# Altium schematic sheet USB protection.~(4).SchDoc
size A3; SheetNumber: 3; SheetTotal: 4
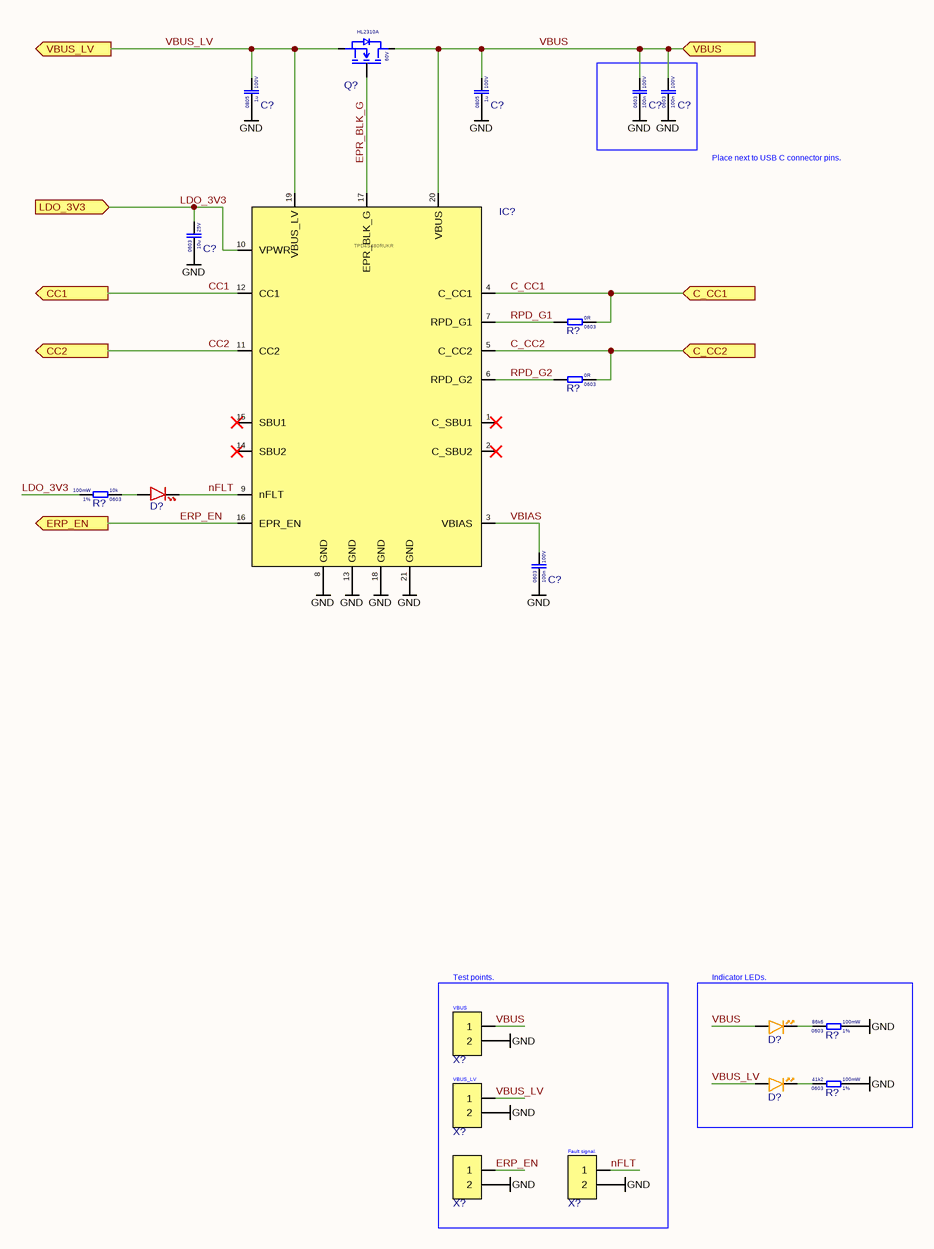
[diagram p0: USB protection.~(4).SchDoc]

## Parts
(Parts that share a designator on the sheet are numbered #1, #2 ... from top to bottom, then left to right.)
C?#1  Voltage Rating: 100V  Case Code (Imperial): 0805  Capacitance: 1u  [Cap_0805]  (hidden comment: CC0805KKX7R0BB105)
C?#2  Voltage Rating: 100V  Case Code (Imperial): 0805  Capacitance: 1u  [Cap_0805]  (hidden comment: CC0805KKX7R0BB105)
C?#3  Voltage Rating: 100V  Case Code (Imperial): 0603  Capacitance: 100n  [CAP 0603]  (hidden comment: CC0603KRX7R0BB104)
C?#4  Voltage Rating: 100V  Case Code (Imperial): 0603  Capacitance: 100n  [CAP 0603]  (hidden comment: CC0603KRX7R0BB104)
C?#5  Voltage Rating: 25V  Case Code (Imperial): 0603  Capacitance: 10u  [CAP 0603]  (hidden comment: CL10A106MA8NRNC)
C?#6  Voltage Rating: 100V  Case Code (Imperial): 0603  Capacitance: 100n  [CAP 0603]  (hidden comment: CC0603KRX7R0BB104)
D?#1  XL-1608SURC-06  [DIODE_0603_RED]  (value not drawn)
D?#2  XL-1608UOC-06  [DIODE_0603_ORANGE]  (value not drawn)
D?#3  XL-1608UOC-06  [DIODE_0603_ORANGE]  (value not drawn)
IC?  TPD4S480RUKR  [WQFN (20)]
Q?  Voltage: 60V  [SOT-23 GSD]  (hidden comment: HL2310A)
R?#1  Resistance: 0R  Case Code (Imperial): 0603  [RES_0603]  (hidden comment: 0603WAF0000T5E)
R?#2  Resistance: 0R  Case Code (Imperial): 0603  [RES_0603]  (hidden comment: 0603WAF0000T5E)
R?#3  Resistance Tolerance: 1%  Resistance: 10k  Power Rating: 100mW  Case Code (Imperial): 0603  [RES_0603]  (hidden comment: 0603WAF1002T5E)
R?#4  Resistance Tolerance: 1%  Resistance: 86k6  Power Rating: 100mW  Case Code (Imperial): 0603  [RES_0603]  (hidden comment: 0603WAF8662T5E)
R?#5  Resistance Tolerance: 1%  Resistance: 41k2  Power Rating: 100mW  Case Code (Imperial): 0603  [RES_0603]  (hidden comment: 0603WAF4122T5E)
X?#1  ZX-PZ1.27-1-2PZZ  [Pin header 1x2 1.27mmP THT Vertical]  (value not drawn)
X?#2  ZX-PZ1.27-1-2PZZ  [Pin header 1x2 1.27mmP THT Vertical]  (value not drawn)
X?#3  ZX-PZ1.27-1-2PZZ  [Pin header 1x2 1.27mmP THT Vertical]  (value not drawn)
X?#4  ZX-PZ1.27-1-2PZZ  [Pin header 1x2 1.27mmP THT Vertical]  (value not drawn)

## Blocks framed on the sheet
Test points.: X?#1-X?#4
Indicator LEDs.: D?#2 D?#3 R?#4 R?#5

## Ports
C_CC1 (in, see CHARGER[7B]), C_CC2 (in, see CHARGER[7B]), CC1 (out, see CHARGER[6B]), CC2 (out, see CHARGER[6B]), ERP_EN (out, see CHARGER[6B]), LDO_3V3 (in, see CHARGER[6C]), VBUS (in, see CHARGER[7B]), VBUS_LV (out, see CHARGER[6B])

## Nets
GND: C?#1.1 C?#2.1 C?#3.1 C?#4.1 C?#5.1 C?#6.1 IC?.8(GND) IC?.13(GND) IC?.18(GND) IC?.21(GND) R?#4.2 R?#5.2 X?#1.2 X?#2.2 X?#3.2 X?#4.2
C_CC1: IC?.4(C_CC1) R?#1.1 ; port C_CC1
C_CC2: IC?.5(C_CC2) R?#2.1 ; port C_CC2
CC1: IC?.12(CC1) ; port CC1
CC2: IC?.11(CC2) ; port CC2
EPR_BLK_G: IC?.17(EPR_BLK_G) Q?.G
ERP_EN: IC?.16(EPR_EN) X?#3.1 ; port ERP_EN
LDO_3V3: C?#5.2 IC?.10(VPWR) R?#3.2 ; port LDO_3V3
nFLT: D?#1.K IC?.9(nFLT) X?#4.1
RPD_G1: IC?.7(RPD_G1) R?#1.2
RPD_G2: IC?.6(RPD_G2) R?#2.2
VBIAS: C?#6.2 IC?.3(VBIAS)
VBUS: C?#2.2 C?#3.2 C?#4.2 D?#2.A IC?.20(VBUS) Q?.D X?#1.1 ; port VBUS
VBUS_LV: C?#1.2 D?#3.A IC?.19(VBUS_LV) Q?.S X?#2.1 ; port VBUS_LV
NetD?#1_A: D?#1.A R?#3.1
NetD?#2_K: D?#2.K R?#4.1
NetD?#3_K: D?#3.K R?#5.1

Not connected (* = marked no-connect by the designer): IC? 1(C_SBU1)* 2(C_SBU2)* 14(SBU2)* 15(SBU1)*

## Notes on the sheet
- Place next to USB C connector pins.
- (near X?#1) VBUS
- (near X?#2) VBUS_LV
- (near X?#4) Fault signal.

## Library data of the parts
C?#1 C?#2 = CC0805KKX7R0BB105: Cap 1uF 100V 0805 X7R; Manufacturer: Yageo
C?#3 C?#4 C?#6 = CC0603KRX7R0BB104: Cap 100nF 100V 0603 X7R; Manufacturer: YAGEO
C?#5 = CL10A106MA8NRNC: Cap 10uF 25V 0603 X5R; Manufacturer: Samsung
D?#1 = XL-1608SURC-06: LED Red 0603 25mA; Manufacturer: Xinglight
D?#2 D?#3 = XL-1608UOC-06: LED Orange 0603 20mA; Manufacturer: XINGLIGHT
IC? = TPD4S480RUKR: USB PD protection IC; Manufacturer: Texas Instruments
Q? = HL2310A: nMOS 60V 3A SOT-23; Manufacturer: hongjiacheng
R?#1 R?#2 = 0603WAF0000T5E: Res 0R 0603 1% 100mW 75V; Manufacturer: UNI-ROYAL
R?#3 = 0603WAF1002T5E: Res 10k 0603 1% 100mW 75V; Manufacturer: Uni-Royal
R?#4 = 0603WAF8662T5E: Res 86k6 0603 1% 100mW 75V; Manufacturer: Uni-Royal
R?#5 = 0603WAF4122T5E: Res 41k2 0603 1% 100mW 75V; Manufacturer: Uni-Royal
X?#1-X?#4 = ZX-PZ1.27-1-2PZZ: Pin header 1x2 1.27mmP THT Vertical; Manufacturer: Megastar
